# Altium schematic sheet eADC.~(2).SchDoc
size A4; SheetNumber: 6; SheetTotal: 7
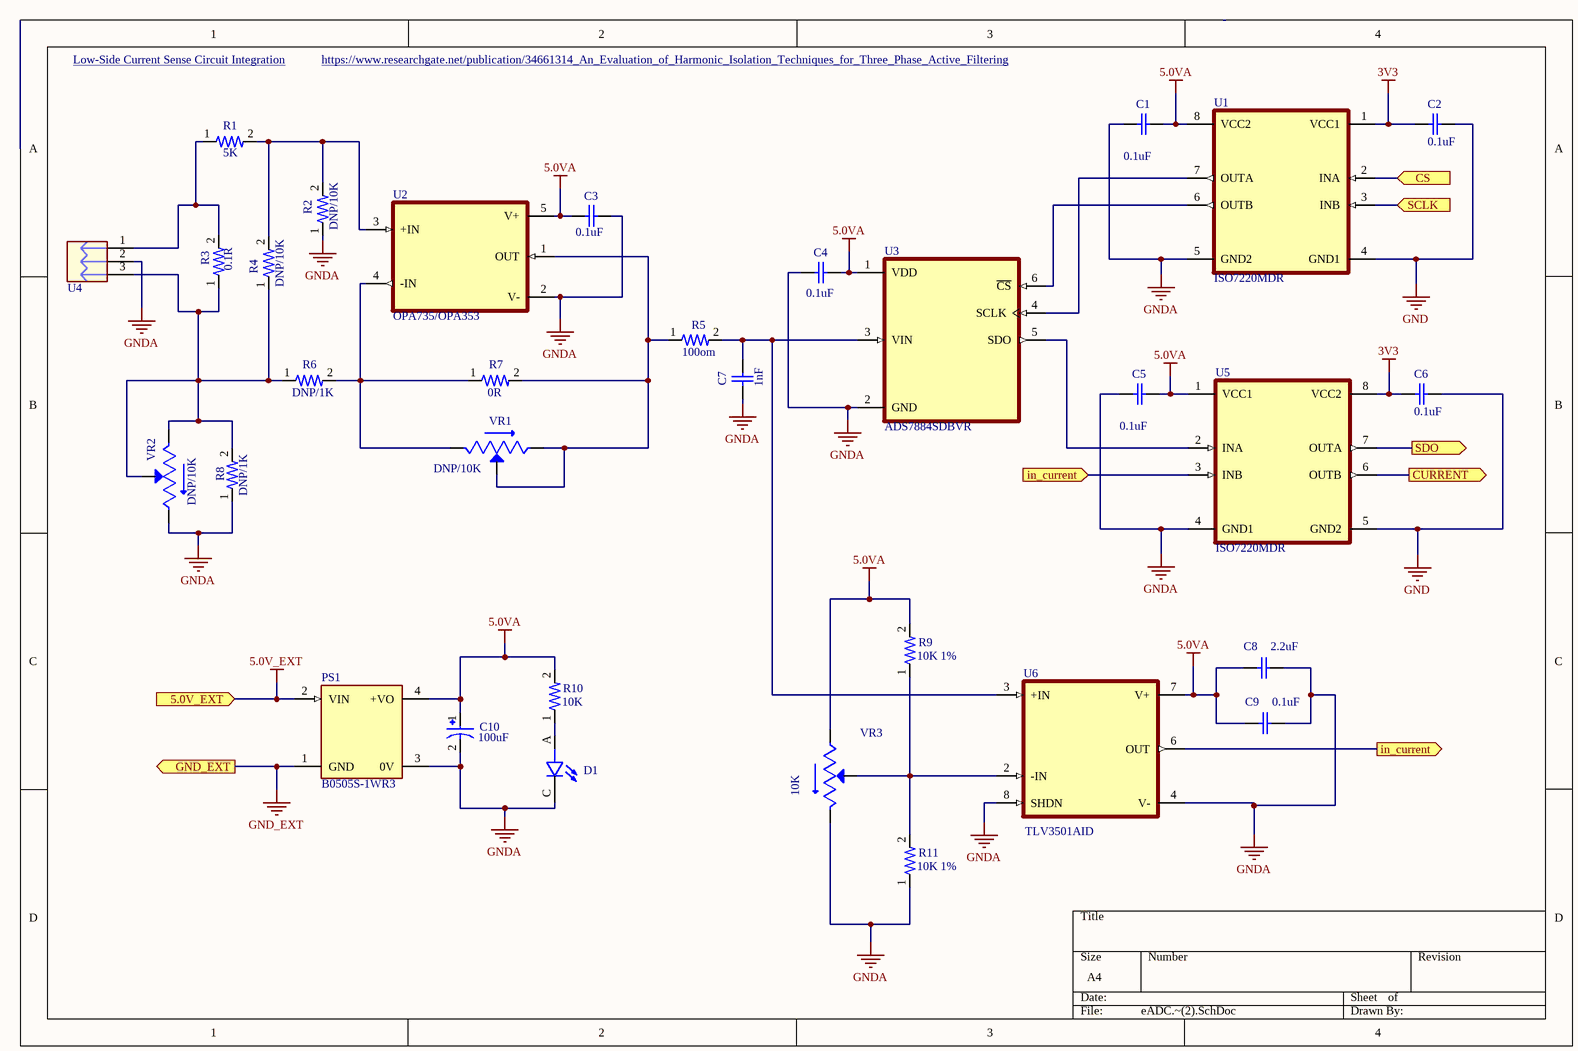
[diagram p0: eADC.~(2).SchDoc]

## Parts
C1  0.1uF  [CAP_0603]
C2  0.1uF  [CAP_0603]
C3  0.1uF  [CAP_0603]
C4  0.1uF  [CAP_0603]
C5  0.1uF  [CAP_0603]
C6  0.1uF  [CAP_0603]
C7  1nF  [CAP_0603]
C8  2.2uF  [CAP_0603]
C9  0.1uF  [CAP_0603]
C10  100uF  [CAP_TYPE_D]
D1  led_0603  [led_0603]  (value not drawn)
PS1  B0505S-1WR3  [B0505S-1WR3]
R1  5K  [RESC1608X50N]
R2  DNP/10K  [RESC1608X50N]
R3  0.1R  [RES_2512]
R4  DNP/10K  [RESC1608X50N]
R5  100om  [RESC1608X50N]
R6  DNP/1K  [RESC1608X50N]
R7  0R  [RESC1608X50N]
R8  DNP/1K  [RESC1608X50N]
R9  10K 1%  [RESC1608X50N]
R10  10K  [RESC1608X50N]
R11  10K 1%  [RESC1608X50N]
U1  ISO7220MDR  [ISO7220MDR]
U2  OPA735/OPA353  [OPA735AIDBVR]
U3  ADS7884SDBVR  [ADS7884SDBVR]
U4  DG129-5.0-03P  [DG129-5.0-03P]  (value not drawn)
U5  ISO7220MDR  [ISO7220MDR]
U6  TLV3501AID  [TLV3501AID]
VR1  DNP/10K  [TRIM_3296W-1-250]
VR2  DNP/10K  [TRIM_3296W-1-250]
VR3  10K  [TRIM_3296W-1-250]

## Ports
5.0V_EXT (in), CS (in), CURRENT (out), GND_EXT (out), in_current (in), in_current (out), SCLK (in), SDO (out)

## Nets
3V3: C2.2 C6.2 U1.1(VCC1) U5.8(VCC2)
5.0V_EXT: PS1.2(VIN) ; port 5.0V_EXT
5.0VA: C1.1 C3.2 C4.1 C5.1 C8.2 C9.2 C10.1 PS1.4(+VO) R9.2 R10.2 U1.8(VCC2) U2.5(V+) U3.1(VDD) U5.1(VCC1) U6.7(V+) VR3.1(CCW)
GND: C2.1 C6.1 U1.4(GND1) U5.5(GND2)
GND_EXT: PS1.1(GND) ; port GND_EXT
GNDA: C1.2 C3.1 C4.2 C5.2 C7.2 C8.1 C9.1 C10.2 D1.C PS1.3(0V) R2.1 R8.1 R11.1 U1.5(GND2) U2.2(V-) U3.2(GND) U4.2 U5.4(GND1) U6.4(V-) U6.8(SHDN) VR2.3(CW) VR3.3(CW)
CS: U1.2(INA) ; port CS
CURRENT: U5.6(OUTB) ; port CURRENT
in_current: U5.3(INB) U6.6(OUT) ; port in_current
SCLK: U1.3(INB) ; port SCLK
SDO: U5.7(OUTA) ; port SDO
NetC7_1: C7.1 R5.2 U3.3(VIN) U6.3(+IN)
NetD1_A: D1.A R10.1
NetR1_1: R1.1 R3.2 U4.1
NetR1_2: R1.2 R2.2 R4.2 U2.3(+IN)
NetR3_1: R3.1 R4.1 R6.1 R8.2 U4.3 VR2.1(CCW) VR2.2(WIPER)
NetR5_1: R5.1 R7.2 U2.1(OUT) VR1.2(WIPER) VR1.3(CW)
NetR6_2: R6.2 R7.1 U2.4(-IN) VR1.1(CCW)
NetR9_1: R9.1 R11.2 U6.2(-IN) VR3.2(WIPER)
NetU1_6: U1.6(OUTB) U3.6(~{CS})
NetU1_7: U1.7(OUTA) U3.4(SCLK)
NetU3_5: U3.5(SDO) U5.2(INA)

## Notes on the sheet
- Low-Side Current Sense Circuit Integration <https://www.ti.com/lit/an/sboa190/sboa190.pdf?ts=1649158428076&ref_url=https%253A%252F%252Fwww.google.com%252F>
- https://www.researchgate.net/publication/34661314_An_Evaluation_of_Harmonic_Isolation_Techniques_for_Three_Phase_Active_Filtering

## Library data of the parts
C1-C9 = CAP_0603
C10 = CAP_TYPE_D: MP: 25TQC15MV
D1 = led_0603: LED Indication - Discrete 3.1V 0603 _1608 Metric_; MP: LTW-C191TLA; MF: Lite-On
PS1 = B0505S-1WR3: Isolated Module DC DC Converter 1 Output 5V 200mA 4.5V - 5.5V Input; MF: Mornsun America, LLC
R1 R5 R7 R9-R11 = RES_0603: 1% 0.1W; MP: 1-2176071-4
R2 R4 R6 R8 = RES_0603: 1% 0.1W  10mA max; MP: 1-2176071-4
R3 = RES_2512: 2512 1% 1W; MP: 1-2176071-4
U1 U5 = ISO7220MDR: Dual-channel, 2/0, 150-Mbps digital isolator 8-SOIC -40 to 125; MF: Texas Instruments
U2 = OPA735AIDR
U3 = ADS7884SDBVR: 2.7V-5.5V, 10 Bit, 3MSPS, Serial ADC 6-SOT-23 -40 to 125; MF: Texas Instruments
U4 = DG129-5.0-03P: DG129-5.0-03P-14-00AH
VR1-VR3 = 3296W-1-250: 25 Ohms 0.5W, 1/2W PC Pins Through Hole Trimmer Potentiometer Cermet 25 Turn Top Adjustment; MF: Bourns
